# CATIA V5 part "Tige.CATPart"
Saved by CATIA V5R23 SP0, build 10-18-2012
Part number: Tige
Material "Acier": density 7860 kg/m3, Young's modulus 2e+11 Pa, Poisson ratio 0.266, thermal expansion 1.17e-05 1/K
Bounding box of the stored display mesh (mm): x -5 to 5, y -5 to 5, z 0 to 187
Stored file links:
  P:\CORRECTION CAO\Tige.CATPart
  d:\catia_soft\intel_a\reffiles\standard\MetricThickPitch.txt
  C:\Program Files\Dassault Systemes\B23\win_b64\startup\materials\French\Catalog.CATMaterial
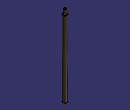
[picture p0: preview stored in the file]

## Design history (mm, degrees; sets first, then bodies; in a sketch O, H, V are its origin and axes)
Body1 (main body)
  Sketch1 on xy-plane, origin (0, 0, 0), H (1, 0, 0), V (0, 1, 0)
    circle A1 centre (0, 0) radius 5
    point P1 (5, 0)
    radius A1 = 5
    coincidence: A1 P1, P1 H
  Pad1: profile Sketch1, direction (0, 0, 1), length 175
  Sketch2 on face of Pad1, origin (0, 0, 175), H (1, 0, 0), V (0, 1, 0)
    circle A1 centre (0, 0) radius 3
    radius A1 = 3
  Pad2: profile Sketch2, direction (0, 0, 1), length 12
  Thread1: "M6", diameter 6, depth 10, pitch 1, on face of Pad2, from face of Pad2
  Chamfer1: length 1, angle 45, on face of Pad2; face of Pad1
